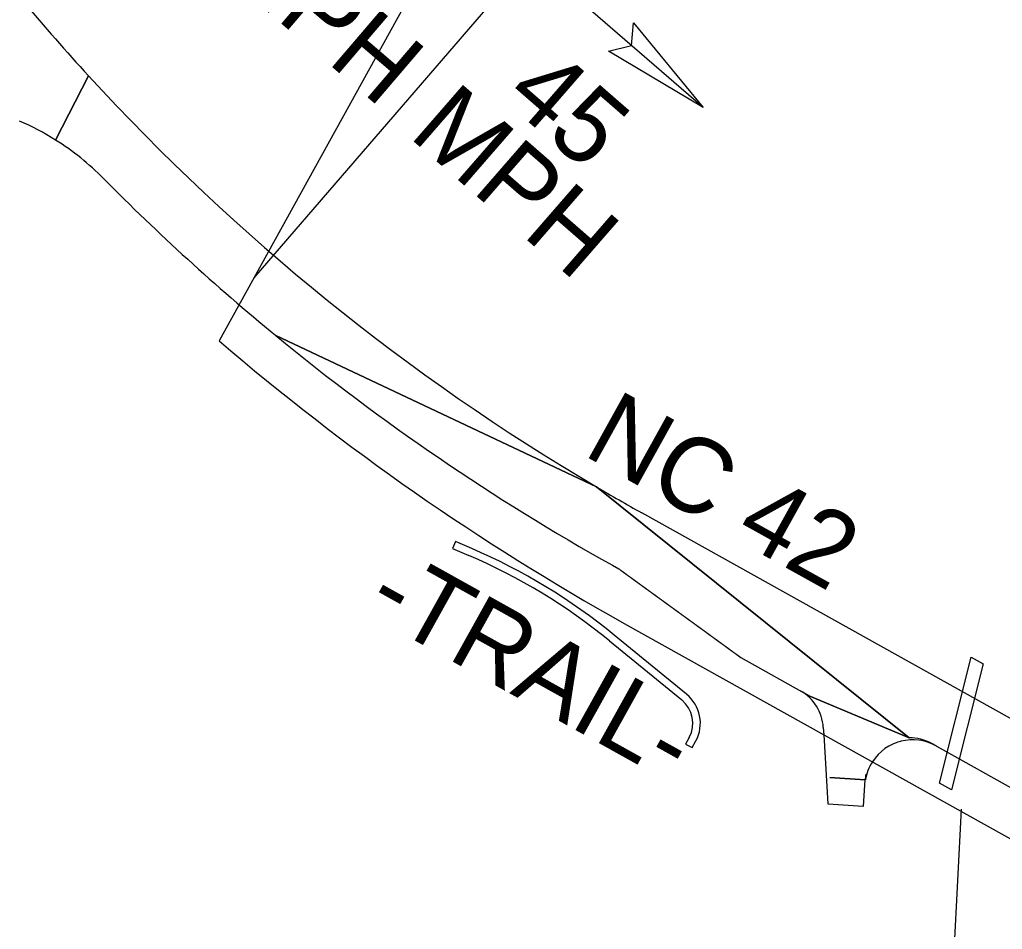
# Model space of a CAD drawing. Extents: x 1754939 to 1770240, y 706534 to 717510.
# Drawn here: x 1764161 to 1764816, y 710711 to 711317 of the extents above; entities that cross this region are included whole.
import ezdxf

# ---------------------------------------------------------------- set-up
doc = ezdxf.new("R2010")
doc.units = 0
for name, color, linetype in [('Old_Level_2', 7, 'Continuous'), ('Prop Conc Curb 8in x 6in', 7, 'Continuous'), ('Prop Guardrail Anchor Unit CELL', 7, 'Continuous'), ('Prop Lane Arrow CELL', 7, 'Continuous'), ('Sheet PE Seal Cell', 7, 'Continuous')]:
    doc.layers.add(name, color=color, linetype=linetype)

msp = doc.modelspace()

# ---------------------------------------------------------------- linework, layer by layer
at = {"layer": 'Old_Level_2'}
for p, q in [((1764500.7619357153, 711357.9790023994), (1764316.7888439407, 711144.670712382)), ((1764616.3924128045, 711258.2505934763), (1764500.7619357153, 711357.9790023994))]:
    msp.add_line(p, q, dxfattribs=at)
at = {"layer": 'Prop Conc Curb 8in x 6in'}
msp.add_lwpolyline([(1764795.0341269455, 710891.8797965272), (1764803.0203391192, 710887.4244250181), (1764781.8650651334, 710803.551280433), (1764773.8788529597, 710808.0066519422)], close=True, dxfattribs=at)
at = {"layer": 'Prop Guardrail Anchor Unit CELL'}
msp.add_lwpolyline([(1764569.9684872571, 711314.6649456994), (1764616.3924128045, 711258.2505934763), (1764553.207059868, 711295.8432945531), (1764568.5337173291, 711299.527527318)], close=True, dxfattribs=at)
at = {"layer": 'Prop Lane Arrow CELL'}
for p, q in [((1764206.50788436, 711279.3591653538), (1764184.572172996, 711236.5169520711)), ((1764184.572172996, 711236.5169520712), (1764206.50788436, 711279.3591653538)), ((1764206.50788436, 711279.3591653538), (1764184.572172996, 711236.5169520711)), ((1764545.1465578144, 711005.4403229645), (1764331.3729196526, 711106.2486042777)), ((1764331.3729196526, 711106.2486042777), (1764545.1465578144, 711005.4403229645)), ((1764545.1465578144, 711005.4403229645), (1764331.3729196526, 711106.2486042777)), ((1764545.1465578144, 711005.4403229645), (1764753.580719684, 710838.1362096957)), ((1764753.580719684, 710838.1362096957), (1764545.1465578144, 711005.4403229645)), ((1764545.1465578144, 711005.4403229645), (1764753.580719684, 710838.1362096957)), ((1765005.946185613, 710747.8971307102), (1764575.413875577, 710988.0837606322)), ((1764451.2799169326, 710968.9492333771), (1764449.3042841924, 710964.3529743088)), ((1764462.0077022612, 710964.3380564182), (1764451.2799169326, 710968.9492333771)), ((1764449.3042841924, 710964.3529743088), (1764460.0332034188, 710959.7444353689)), ((1764555.9260639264, 710953.152038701), (1764560.016777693, 710950.8698992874)), ((1764553.8442640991, 710902.8332157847), (1764602.1192187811, 710863.4230507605)), ((1764605.2811993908, 710867.2962766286), (1764557.0062447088, 710906.7064416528)), ((1764641.4997390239, 710891.6708535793), (1764687.4391823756, 710866.0420219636)), ((1764687.4391823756, 710866.0420219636), (1764681.0933109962, 710869.5822753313)), ((1764753.580719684, 710838.1362096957), (1764687.4391823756, 710866.0420219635)), ((1764687.4391823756, 710866.0420219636), (1764753.580719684, 710838.1362096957)), ((1764753.580719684, 710838.1362096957), (1764687.4391823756, 710866.0420219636)), ((1764696.425195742, 710845.1534161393), (1764696.7146506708, 710840.2557586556)), ((1764607.0882479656, 710838.4621477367), (1764604.6308575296, 710834.0477737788)), ((1764609.0351255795, 710831.6807576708), (1764611.4924858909, 710836.0951478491)), ((1764696.7146506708, 710840.2557586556), (1764699.431948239, 710794.2783319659)), ((1764604.6308575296, 710834.0477737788), (1764609.0351255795, 710831.6807576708)), ((1764768.8901313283, 710834.3430191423), (1764971.7343117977, 710721.1797118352)), ((1764771.6442961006, 710832.8065176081), (1764768.8901313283, 710834.3430191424)), ((1764724.3444232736, 710810.1946227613), (1764700.7841017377, 710811.808661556)), ((1764700.7841017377, 710811.808661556), (1764700.7847700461, 710811.8086167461)), ((1764700.7847700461, 710811.8086167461), (1764724.3444232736, 710810.1946227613)), ((1764723.1427719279, 710792.6539817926), (1764724.3444232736, 710810.1946227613)), ((1764699.431948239, 710794.2783319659), (1764699.5849150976, 710794.2678527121)), ((1764699.5849150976, 710794.2678527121), (1764722.9916014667, 710792.6643379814)), ((1764722.9916014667, 710792.6643379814), (1764723.1427719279, 710792.6539817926)), ((1764722.9916014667, 710792.6643379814), (1764723.1427719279, 710792.6539817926))]:
    msp.add_line(p, q, dxfattribs=at)
for centre, radius, start, end in [((1765296.4629066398, 712280.5574720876), 1480.0000000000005, 220.01406997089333, 222.569602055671), ((1765296.4629066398, 712280.5574720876), 1480.000000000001, 222.56960205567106, 239.49283011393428), ((1764088.7283958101, 711084.1556368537), 180.00000000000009, 57.82781423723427, 66.45710526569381), ((1764088.7283958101, 711084.1556368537), 180.00000000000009, 44.72992861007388, 57.82781423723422), ((1765296.4629066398, 712280.5574720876), 1519.9999999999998, 224.7299187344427, 230.5853833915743), ((1765296.4629066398, 712280.5574720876), 1519.9999999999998, 230.58538339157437, 240.84359769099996), ((1765296.4629066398, 712280.5574720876), 1480.0000000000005, 239.49283011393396, 240.84359769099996), ((1764304.0477959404, 710596.8483722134), 395, 50.772873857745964, 66.74027714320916), ((1764304.0477959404, 710596.8483722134), 400.0000000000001, 50.77287385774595, 66.74027714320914), ((1764666.4774522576, 710843.3834838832), 30.000000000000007, 3.3822856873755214, 60.843597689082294), ((1764589.4712963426, 710847.9301472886), 20, 331.7447762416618, 50.77287385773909), ((1764589.4712963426, 710847.9301472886), 25.000000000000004, 331.7447762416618, 50.772873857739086), ((1764756.0540467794, 710804.8611400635), 32.000000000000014, 60.84359768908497, 147.2602760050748), ((1764754.2742725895, 710808.1442276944), 30.000000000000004, 60.84359768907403, 91.32470649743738), ((1764754.2742725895, 710808.1442276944), 30.000000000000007, 60.84359768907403, 91.32470649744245), ((1764756.0540467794, 710804.8611400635), 32.000000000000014, 147.26027600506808, 170.47903107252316), ((1764754.2742725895, 710808.1442276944), 30.000000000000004, 168.78937872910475, 176.0809787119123)]:
    msp.add_arc(centre, radius, start, end, dxfattribs=at)
for points in [[(1764560.016777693, 710950.8698992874), (1764560.3838180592, 710950.6032369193), (1764560.7508584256, 710950.3365745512), (1764561.117898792, 710950.0699121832), (1764561.3014189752, 710949.9365809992), (1764561.4849391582, 710949.8032498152), (1764561.6684593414, 710949.6699186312), (1764561.8519795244, 710949.5365874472), (1764562.0354997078, 710949.4032562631), (1764562.219019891, 710949.2699250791), (1764562.4025400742, 710949.1365938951), (1764562.5860602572, 710949.0032627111), (1764562.7695804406, 710948.8699315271), (1764562.9531006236, 710948.736600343), (1764563.136620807, 710948.603269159), (1764563.3201409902, 710948.4699379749), (1764563.5036611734, 710948.3366067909), (1764563.6871813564, 710948.203275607), (1764563.8707015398, 710948.0699444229), (1764564.0542217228, 710947.936613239), (1764564.2377419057, 710947.8032820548), (1764564.4212620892, 710947.6699508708), (1764564.6047822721, 710947.5366196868), (1764564.7883024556, 710947.4032885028), (1764564.9718226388, 710947.2699573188), (1764565.155342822, 710947.1366261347), (1764565.338863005, 710947.0032949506), (1764565.5223831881, 710946.8699637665), (1764565.705903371, 710946.7366325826), (1764565.8894235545, 710946.6033013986), (1764566.0729437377, 710946.4699702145), (1764566.256463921, 710946.3366390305), (1764566.439984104, 710946.2033078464), (1764566.6235042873, 710946.0699766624), (1764566.8070244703, 710945.9366454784), (1764566.9905446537, 710945.8033142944), (1764567.174064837, 710945.6699831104), (1764567.3575850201, 710945.5366519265), (1764567.541105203, 710945.4033207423), (1764567.7246253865, 710945.2699895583), (1764567.9081455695, 710945.1366583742), (1764568.0916657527, 710945.0033271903), (1764568.2751859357, 710944.8699960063), (1764568.4587061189, 710944.7366648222), (1764568.6422263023, 710944.6033336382), (1764568.8257464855, 710944.4700024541), (1764569.0092666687, 710944.3366712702), (1764569.1927868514, 710944.2033400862), (1764569.3763070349, 710944.0700089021), (1764569.5598272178, 710943.9366777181), (1764569.7433474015, 710943.8033465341), (1764569.9268675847, 710943.67001535), (1764570.110387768, 710943.536684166), (1764570.2939079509, 710943.4033529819), (1764570.477428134, 710943.2700217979), (1764570.660948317, 710943.1366906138), (1764570.8444685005, 710943.0033594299), (1764571.0279886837, 710942.8700282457), (1764571.2115088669, 710942.7366970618), (1764571.3950290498, 710942.6033658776), (1764571.578549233, 710942.4700346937), (1764571.762069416, 710942.3367035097), (1764571.9455895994, 710942.2033723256), (1764572.1291097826, 710942.0700411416), (1764572.3126299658, 710941.9367099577), (1764572.4961501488, 710941.8033787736), (1764572.679670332, 710941.6700475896), (1764572.863190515, 710941.5367164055), (1764573.0467106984, 710941.4033852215), (1764573.2302308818, 710941.2700540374), (1764573.3525776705, 710941.1811665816), (1764573.4749244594, 710941.0922791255), (1764573.5972712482, 710941.0033916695)], [(1764573.5972712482, 710941.0033916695), (1764573.6584446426, 710940.9589479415), (1764573.719618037, 710940.9145042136), (1764573.7807914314, 710940.8700604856), (1764573.9643116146, 710940.7367293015), (1764574.1478317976, 710940.6033981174), (1764574.3313519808, 710940.4700669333), (1764574.5148721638, 710940.3367357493), (1764574.6983923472, 710940.2034045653), (1764574.8819125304, 710940.0700733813), (1764575.0654327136, 710939.9367421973), (1764575.2489528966, 710939.8034110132), (1764575.4324730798, 710939.6700798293), (1764575.6159932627, 710939.5367486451), (1764575.7995134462, 710939.4034174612), (1764575.9830336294, 710939.270086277), (1764576.1665538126, 710939.136755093), (1764576.3500739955, 710939.003423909), (1764576.533594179, 710938.8700927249), (1764576.717114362, 710938.7367615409), (1764576.9006345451, 710938.6034303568), (1764577.0841547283, 710938.4700991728), (1764577.2676749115, 710938.3367679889), (1764577.4511950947, 710938.2034368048), (1764577.634715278, 710938.0701056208), (1764577.8182354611, 710937.9367744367), (1764578.001755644, 710937.8034432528), (1764578.1852758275, 710937.6701120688), (1764578.3687960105, 710937.5367808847), (1764578.5523161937, 710937.4034497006), (1764578.735836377, 710937.2701185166), (1764578.91935656, 710937.1367873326), (1764579.102876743, 710937.0034561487), (1764579.2863969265, 710936.8701249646), (1764579.4699171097, 710936.7367937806), (1764579.6534372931, 710936.6034625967), (1764579.8369574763, 710936.4701314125), (1764580.0204776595, 710936.3368002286), (1764580.2039978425, 710936.2034690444), (1764580.3875180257, 710936.0701378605), (1764580.5710382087, 710935.9368066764), (1764580.754558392, 710935.8034754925), (1764580.9380785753, 710935.6701443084), (1764581.1215987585, 710935.5368131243), (1764581.3051189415, 710935.4034819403), (1764581.4886391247, 710935.2701507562), (1764581.6721593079, 710935.1368195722), (1764581.8556794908, 710935.003488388), (1764582.0391996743, 710934.8701572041), (1764582.2227198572, 710934.7368260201), (1764582.4062400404, 710934.6034948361), (1764582.5897602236, 710934.4701636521), (1764582.7732804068, 710934.336832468), (1764582.95680059, 710934.203501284), (1764583.1403207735, 710934.0701701), (1764583.3238409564, 710933.9368389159), (1764583.5073611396, 710933.8035077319), (1764583.6908813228, 710933.670176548), (1764583.874401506, 710933.5368453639), (1764584.057921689, 710933.4035141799), (1764584.2414418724, 710933.2701829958), (1764584.4249620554, 710933.1368518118), (1764584.6084822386, 710933.0035206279), (1764584.7920024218, 710932.8701894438), (1764584.975522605, 710932.7368582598), (1764585.159042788, 710932.6035270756), (1764585.3425629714, 710932.4701958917), (1764585.5260831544, 710932.3368647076), (1764585.7096033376, 710932.2035335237), (1764585.893123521, 710932.0702023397), (1764586.076643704, 710931.9368711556), (1764586.2601638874, 710931.8035399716), (1764586.4436840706, 710931.6702087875), (1764586.6272042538, 710931.5368776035), (1764586.8107244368, 710931.4035464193), (1764586.9942446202, 710931.2702152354), (1764587.0554180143, 710931.2257715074), (1764587.1165914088, 710931.1813277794), (1764587.1777648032, 710931.1368840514)], [(1764587.1777648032, 710931.1368840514), (1764587.3001115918, 710931.0479965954), (1764587.4224583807, 710930.9591091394), (1764587.5448051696, 710930.8702216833), (1764587.7283253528, 710930.7368904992), (1764587.9118455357, 710930.6035593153), (1764588.0953657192, 710930.4702281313), (1764588.2788859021, 710930.3368969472), (1764588.4624060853, 710930.2035657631), (1764588.6459262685, 710930.0702345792), (1764588.8294464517, 710929.9369033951), (1764589.0129666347, 710929.8035722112), (1764589.1964868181, 710929.6702410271), (1764589.380007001, 710929.5369098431), (1764589.5635271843, 710929.403578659), (1764589.7470473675, 710929.270247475), (1764589.9305675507, 710929.136916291), (1764590.114087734, 710929.0035851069), (1764590.2976079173, 710928.870253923), (1764590.4811281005, 710928.7369227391), (1764590.6646482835, 710928.6035915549), (1764590.8481684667, 710928.4702603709), (1764591.0316886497, 710928.3369291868), (1764591.215208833, 710928.2035980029), (1764591.3987290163, 710928.0702668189), (1764591.5822491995, 710927.9369356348), (1764591.7657693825, 710927.8036044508), (1764591.949289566, 710927.6702732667), (1764592.1328097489, 710927.5369420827), (1764592.316329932, 710927.4036108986), (1764592.4998501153, 710927.2702797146), (1764592.6833702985, 710927.1369485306), (1764592.8668904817, 710927.0036173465), (1764593.050410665, 710926.8702861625), (1764593.233930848, 710926.7369549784), (1764593.4174510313, 710926.6036237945), (1764593.6009712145, 710926.4702926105), (1764593.7844913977, 710926.3369614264), (1764593.9680115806, 710926.2036302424), (1764594.151531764, 710926.0702990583), (1764594.335051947, 710925.9369678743), (1764594.5185721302, 710925.8036366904), (1764594.7020923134, 710925.6703055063), (1764594.8856124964, 710925.5369743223), (1764595.0691326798, 710925.4036431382), (1764595.252652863, 710925.2703119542), (1764595.4361730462, 710925.1369807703), (1764595.6196932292, 710925.0036495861), (1764595.8032134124, 710924.8703184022), (1764595.9867335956, 710924.7369872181), (1764596.170253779, 710924.6036560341), (1764596.3537739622, 710924.4703248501), (1764596.5372941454, 710924.336993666), (1764596.7208143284, 710924.2036624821), (1764596.9043345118, 710924.070331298), (1764597.0878546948, 710923.937000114), (1764597.271374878, 710923.80366893), (1764597.4548950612, 710923.6703377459), (1764597.6384152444, 710923.5370065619), (1764597.8219354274, 710923.4036753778), (1764598.0054556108, 710923.2703441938), (1764598.1889757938, 710923.1370130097), (1764598.372495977, 710923.0036818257), (1764598.55601616, 710922.8703506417), (1764598.7395363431, 710922.7370194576), (1764598.9230565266, 710922.6036882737), (1764599.1065767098, 710922.4703570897), (1764599.290096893, 710922.3370259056), (1764599.473617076, 710922.2036947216), (1764599.6571372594, 710922.0703635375), (1764599.8406574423, 710921.9370323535), (1764600.0241776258, 710921.8037011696), (1764600.207697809, 710921.6703699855), (1764600.3912179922, 710921.5370388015), (1764600.5747381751, 710921.4037076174), (1764600.7582583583, 710921.2703764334)], [(1764600.7582583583, 710921.2703764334), (1764600.9417785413, 710921.1370452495), (1764601.1252987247, 710921.0037140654), (1764601.308818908, 710920.8703828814), (1764601.4923390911, 710920.7370516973), (1764601.6758592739, 710920.6037205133), (1764601.8593794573, 710920.4703893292), (1764602.0428996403, 710920.3370581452), (1764602.2264198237, 710920.2037269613), (1764602.409940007, 710920.0703957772), (1764602.59346019, 710919.9370645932), (1764602.7769803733, 710919.8037334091), (1764602.9605005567, 710919.670402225), (1764603.14402074, 710919.537071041), (1764603.327540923, 710919.403739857), (1764603.511061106, 710919.270408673), (1764603.694581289, 710919.1370774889), (1764603.8781014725, 710919.0037463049), (1764604.0616216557, 710918.8704151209), (1764604.245141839, 710918.7370839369), (1764604.4286620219, 710918.6037527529), (1764604.612182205, 710918.4704215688), (1764604.795702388, 710918.3370903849), (1764604.9792225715, 710918.2037592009), (1764605.1627427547, 710918.0704280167), (1764605.3462629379, 710917.9370968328), (1764605.5297831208, 710917.8037656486), (1764605.713303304, 710917.6704344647), (1764605.8968234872, 710917.5371032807), (1764606.0803436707, 710917.4037720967), (1764606.2638638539, 710917.2704409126), (1764606.447384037, 710917.1371097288), (1764606.63090422, 710917.0037785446), (1764606.8144244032, 710916.8704473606), (1764606.9979445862, 710916.7371161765), (1764607.1814647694, 710916.6037849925), (1764607.3649849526, 710916.4704538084), (1764607.5485051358, 710916.3371226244), (1764607.732025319, 710916.2037914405), (1764607.9155455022, 710916.0704602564), (1764608.0990656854, 710915.9371290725), (1764608.2825858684, 710915.8037978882), (1764608.4661060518, 710915.6704667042), (1764608.6496262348, 710915.5371355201), (1764608.8331464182, 710915.4038043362), (1764609.0166666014, 710915.2704731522), (1764609.2001867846, 710915.1371419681), (1764609.3837069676, 710915.0038107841), (1764609.567227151, 710914.8704796), (1764609.750747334, 710914.7371484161), (1764609.9342675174, 710914.6038172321), (1764610.1177877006, 710914.470486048), (1764610.3013078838, 710914.337154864), (1764610.4848280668, 710914.2038236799), (1764610.66834825, 710914.0704924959), (1764610.851868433, 710913.9371613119), (1764611.0353886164, 710913.8038301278), (1764611.2189087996, 710913.6704989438), (1764611.4024289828, 710913.5371677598), (1764611.5859491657, 710913.4038365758), (1764611.769469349, 710913.2705053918), (1764611.9529895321, 710913.1371742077), (1764612.136509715, 710913.0038430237), (1764612.3200298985, 710912.8705118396), (1764612.5035500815, 710912.7371806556), (1764612.687070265, 710912.6038494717), (1764612.8705904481, 710912.4705182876), (1764613.0541106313, 710912.3371871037), (1764613.2376308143, 710912.2038559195), (1764613.4211509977, 710912.0705247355), (1764613.6046711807, 710911.9371935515), (1764613.788191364, 710911.8038623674), (1764613.971711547, 710911.6705311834), (1764614.0940583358, 710911.5816437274), (1764614.2164051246, 710911.4927562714), (1764614.3387519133, 710911.4038688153)], [(1764614.3387519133, 710911.4038688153), (1764614.3999253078, 710911.3594250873), (1764614.4610987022, 710911.3149813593), (1764614.5222720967, 710911.2705376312), (1764614.7057922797, 710911.1372064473), (1764614.889312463, 710911.0038752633), (1764615.0728326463, 710910.8705440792), (1764615.2563528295, 710910.7372128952), (1764615.4398730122, 710910.6038817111), (1764615.6233931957, 710910.4705505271), (1764615.8069133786, 710910.337219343), (1764615.990433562, 710910.2038881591), (1764616.1739537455, 710910.0705569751), (1764616.3574739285, 710909.9372257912), (1764616.5409941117, 710909.803894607), (1764616.7245142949, 710909.670563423), (1764616.908034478, 710909.5372322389), (1764617.091554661, 710909.403901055), (1764617.2750748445, 710909.270569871), (1764617.4585950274, 710909.1372386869), (1764617.6421152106, 710909.0039075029), (1764617.8256353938, 710908.8705763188), (1764618.009155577, 710908.7372451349), (1764618.19267576, 710908.6039139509), (1764618.3761959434, 710908.4705827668), (1764618.5597161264, 710908.3372515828), (1764618.7432363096, 710908.2039203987), (1764618.9267564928, 710908.0705892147), (1764619.110276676, 710907.9372580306), (1764619.2937968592, 710907.8039268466), (1764619.4773170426, 710907.6705956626), (1764619.6608372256, 710907.5372644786), (1764619.8443574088, 710907.4039332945), (1764620.027877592, 710907.2706021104), (1764620.2113977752, 710907.1372709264), (1764620.3949179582, 710907.0039397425), (1764620.5784381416, 710906.8706085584), (1764620.7619583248, 710906.7372773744), (1764620.9454785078, 710906.6039461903), (1764621.1289986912, 710906.4706150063), (1764621.3125188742, 710906.3372838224), (1764621.4960390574, 710906.2039526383), (1764621.6795592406, 710906.0706214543), (1764621.8630794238, 710905.9372902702), (1764622.0465996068, 710905.8039590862), (1764622.2301197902, 710905.6706279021), (1764622.4136399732, 710905.5372967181), (1764622.5971601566, 710905.4039655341), (1764622.7806803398, 710905.2706343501), (1764622.964200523, 710905.1373031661), (1764623.147720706, 710905.003971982), (1764623.3312408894, 710904.870640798), (1764623.5147610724, 710904.737309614), (1764623.6982812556, 710904.60397843), (1764623.8818014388, 710904.470647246), (1764624.065321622, 710904.337316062), (1764624.248841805, 710904.2039848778), (1764624.4323619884, 710904.0706536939), (1764624.6158821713, 710903.9373225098), (1764624.7994023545, 710903.8039913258), (1764624.9829225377, 710903.6706601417), (1764625.1664427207, 710903.5373289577), (1764625.3499629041, 710903.4039977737), (1764625.5334830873, 710903.2706665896), (1764625.7170032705, 710903.1373354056), (1764625.9005234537, 710903.0040042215), (1764626.0840436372, 710902.8706730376), (1764626.2675638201, 710902.7373418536), (1764626.4510840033, 710902.6040106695), (1764626.6346041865, 710902.4706794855), (1764626.8181243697, 710902.3373483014), (1764627.0016445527, 710902.2040171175), (1764627.1851647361, 710902.0706859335), (1764627.368684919, 710901.9373547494), (1764627.5522051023, 710901.8040235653), (1764627.7357252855, 710901.6706923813), (1764627.7968986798, 710901.6262486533), (1764627.8580720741, 710901.5818049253), (1764627.9192454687, 710901.5373611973)], [(1764627.9192454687, 710901.5373611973), (1764628.0415922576, 710901.4484737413), (1764628.1639390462, 710901.3595862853), (1764628.286285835, 710901.2706988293), (1764628.469806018, 710901.1373676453), (1764628.653326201, 710901.0040364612), (1764628.8368463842, 710900.8707052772), (1764629.0203665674, 710900.7373740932), (1764629.203886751, 710900.6040429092), (1764629.3874069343, 710900.4707117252), (1764629.5709271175, 710900.3373805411), (1764629.7544473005, 710900.204049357), (1764629.9379674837, 710900.0707181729), (1764630.1214876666, 710899.9373869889), (1764630.30500785, 710899.804055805), (1764630.4885280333, 710899.6707246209), (1764630.6720482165, 710899.5373934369), (1764630.8555683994, 710899.4040622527), (1764631.0390885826, 710899.2707310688), (1764631.2226087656, 710899.1373998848), (1764631.406128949, 710899.0040687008), (1764631.5896491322, 710898.8707375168), (1764631.7731693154, 710898.7374063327), (1764631.9566894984, 710898.6040751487), (1764632.1402096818, 710898.4707439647), (1764632.3237298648, 710898.3374127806), (1764632.5072500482, 710898.2040815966), (1764632.6907702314, 710898.0707504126), (1764632.8742904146, 710897.9374192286), (1764633.0578105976, 710897.8040880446), (1764633.241330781, 710897.6707568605), (1764633.4248509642, 710897.5374256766), (1764633.6083711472, 710897.4040944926), (1764633.7918913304, 710897.2707633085), (1764633.9754115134, 710897.1374321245), (1764634.1589316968, 710897.0041009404), (1764634.34245188, 710896.8707697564), (1764634.5259720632, 710896.7374385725), (1764634.7094922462, 710896.6041073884), (1764634.8930124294, 710896.4707762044), (1764635.0765326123, 710896.3374450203), (1764635.2600527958, 710896.2041138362), (1764635.443572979, 710896.0707826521), (1764635.6270931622, 710895.9374514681), (1764635.8106133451, 710895.804120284), (1764635.9941335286, 710895.6707891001), (1764636.1776537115, 710895.5374579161), (1764636.361173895, 710895.404126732), (1764636.5446940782, 710895.270795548), (1764636.7282142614, 710895.1374643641), (1764636.9117344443, 710895.00413318), (1764637.0952546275, 710894.870801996), (1764637.2787748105, 710894.7374708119), (1764637.4622949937, 710894.6041396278), (1764637.645815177, 710894.4708084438), (1764637.82933536, 710894.3374772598), (1764638.0128555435, 710894.2041460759), (1764638.1963757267, 710894.0708148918), (1764638.37989591, 710893.9374837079), (1764638.5634160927, 710893.8041525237), (1764638.746936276, 710893.6708213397), (1764638.930456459, 710893.5374901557), (1764639.1139766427, 710893.4041589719), (1764639.297496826, 710893.2708277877), (1764639.4810170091, 710893.1374966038), (1764639.6645371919, 710893.0041654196), (1764639.8480573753, 710892.8708342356), (1764640.0315775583, 710892.7375030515), (1764640.2150977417, 710892.6041718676), (1764640.398617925, 710892.4708406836), (1764640.582138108, 710892.3375094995), (1764640.7656582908, 710892.2041783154), (1764640.9491784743, 710892.0708471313), (1764641.1326986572, 710891.9375159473), (1764641.3162188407, 710891.8041847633), (1764641.4997390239, 710891.6708535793)], [(1764724.8466986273, 710813.9767135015), (1764724.740141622, 710812.8718629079), (1764724.6252828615, 710811.5994102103), (1764724.5096860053, 710810.3187805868), (1764724.4948425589, 710810.1542137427)]]:
    msp.add_open_spline(points, degree=3, dxfattribs=at)
at = {"layer": 'Sheet PE Seal Cell'}
for p, q in [((1764563.71651618, 710914.4531486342), (1765126.4420396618, 710600.5181804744)), ((1764788.3763938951, 710790.5665720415), (1764759.7292694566, 710249.1353756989))]:
    msp.add_line(p, q, dxfattribs=at)
msp.add_lwpolyline([(1764321.1749904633, 711494.2837680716), (1764417.373225, 711491.3191229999), (1764503.0763180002, 711481.7054750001), (1764430.325364, 711350.0830960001), (1764293.61992176, 711102.753067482)], dxfattribs=at)
msp.add_arc((1765367.5887467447, 712355.3866783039), 1650.0000000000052, 229.39124742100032, 240.84359769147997, dxfattribs=at)

# ---------------------------------------------------------------- texts
at = {"layer": 'Old_Level_2'}
for s, rotation, p in [('MPH', 319.47642526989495, (1764288.557222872, 711353.8361867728)), ('45', 318.9696704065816, (1764482.4582844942, 711263.6247050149)), ('MPH', 318.9696704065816, (1764419.222645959, 711239.116012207))]:
    msp.add_text(s, height=50, rotation=rotation, dxfattribs=at).set_placement(p)
at = {"layer": 'Sheet PE Seal Cell'}
for s, height, rotation, p in [('NC 42', 49.999999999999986, 330.9544115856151, (1764535.2639920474, 711027.1852871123)), ('-TRAIL-', 49.999999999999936, 330.8875446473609, (1764389.5288875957, 710922.2719732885))]:
    msp.add_text(s, height=height, rotation=rotation, dxfattribs=at).set_placement(p)

doc.saveas('drawing.dxf')
